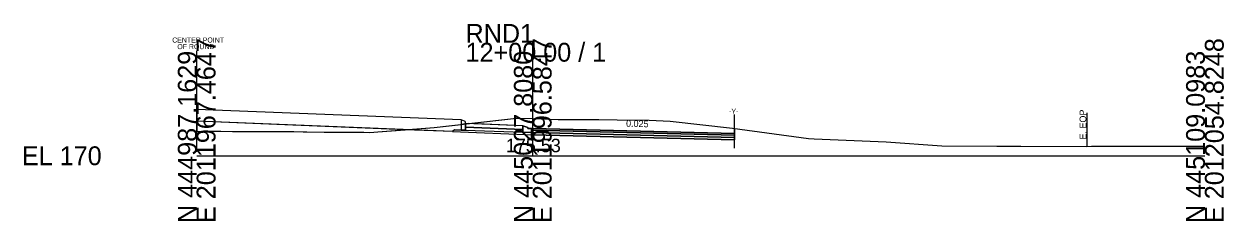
# Model space of a CAD drawing. Extents: x -26 to 153, y -10 to 6017.
# Drawn here: x -25.7 to 152.8, y 3990.3 to 4019.6 of the extents above; entities that cross this region are included whole.
import ezdxf

# ---------------------------------------------------------------- set-up
doc = ezdxf.new("R2010")
doc.units = 0
for name, color, linetype in [('Exist Cross Section Cell', 7, 'Continuous'), ('Exist XS Ground Line', 7, 'Continuous'), ('Prop CMT Conc Surface', 7, 'Continuous'), ('Prop CMT Concrete Structures', 7, 'Continuous'), ('Prop CMT Pvmt Course 1', 7, 'Continuous'), ('Prop CMT Pvmt Course 1 CG', 7, 'Continuous'), ('Prop CMT Pvmt Course 2', 7, 'Continuous'), ('Prop CMT Pvmt Course 3', 7, 'Continuous'), ('Prop CMT Pvmt Surface', 7, 'Continuous'), ('Prop CMT Shear Line', 7, 'Continuous'), ('Prop CMT Shear Line Text', 7, 'Continuous'), ('Prop CMT Slope Grass', 7, 'Continuous'), ('Prop CMT Subgrade Earthwork', 7, 'Continuous'), ('Prop XS Earthwork Shape', 7, 'Continuous'), ('Prop XS Label Text', 7, 'Continuous'), ('Prop XS SE Text', 7, 'Continuous')]:
    doc.layers.add(name, color=color, linetype=linetype)

msp = doc.modelspace()

# ---------------------------------------------------------------- linework, layer by layer
at = {"layer": 'Exist Cross Section Cell'}
for p, q in [((50, 4000), (50, 4016.79)), ((0, 4000), (50, 4000)), ((50, 4000), (150, 4000))]:
    msp.add_line(p, q, dxfattribs=at)
at = {"layer": 'Exist XS Ground Line'}
msp.add_lwpolyline([(0, 4003.62), (0.51, 4003.62), (1.76, 4003.64), (3.57, 4003.66), (5.34, 4003.63), (6.64, 4003.61), (7.81, 4003.62), (9.98, 4003.63), (11.22, 4003.61), (12.43, 4003.6), (12.79, 4003.6), (14.46, 4003.59), (15.85, 4003.57), (16.4, 4003.57), (18.96, 4003.53), (19.68, 4003.53), (20.69, 4003.53), (21.99, 4003.52), (22.86, 4003.51), (23.37, 4003.5), (24.89, 4003.5), (25.76, 4003.44), (26.95, 4003.56), (35.33, 4004.22), (47.6, 4005.58), (48.08, 4005.6), (50, 4005.53), (53.77, 4005.4), (59.84, 4005.39), (62.55, 4005.35), (67.34, 4005.28), (70.42, 4005.13), (79.71, 4004.08), (91.03, 4002.59), (91.86, 4002.53), (102.6, 4002.07), (110.88, 4001.48), (119.04, 4001.41), (122.62, 4001.41), (132.45, 4001.4), (133.12, 4001.41), (134.27, 4001.41), (135.46, 4001.42), (135.96, 4001.42), (136.61, 4001.41), (138.87, 4001.42), (140.9, 4001.42), (141.52, 4001.42), (141.96, 4001.42), (143.31, 4001.43), (145.21, 4001.45), (148.11, 4001.45), (148.68, 4001.44), (149.49, 4001.44), (150, 4001.44)], dxfattribs=at)
at = {"layer": 'Prop CMT Conc Surface'}
for points in [[(40, 4005), (39.96, 4005.1), (39.85, 4005.15), (39.34, 4005.33)], [(40, 4004.83), (40, 4005)], [(50, 4004.04), (49.25, 4004.06), (49.25, 4004.22), (48.5, 4004.47)]]:
    msp.add_lwpolyline(points, dxfattribs=at)
at = {"layer": 'Prop CMT Concrete Structures'}
for points in [[(40, 4005), (39.96, 4005.1), (39.85, 4005.15), (39.34, 4005.33)], [(39.34, 4005.33), (39.34, 4003.83)], [(40, 4004.83), (40, 4005)], [(40, 4003.83), (40, 4004.83)], [(40, 4004.83), (40, 4004.25)], [(48.5, 4004.47), (40, 4004.82)], [(39.34, 4003.83), (40, 4003.83)], [(40, 4004.23), (48.5, 4003.89)], [(50, 4004.04), (49.25, 4004.06), (49.25, 4004.22), (48.5, 4004.47)], [(48.5, 4004.47), (48.5, 4003.49)], [(48.5, 4003.89), (48.5, 4004.47)], [(48.5, 4003.49), (50, 4003.46)], [(50, 4003.46), (50, 4004.04)]]:
    msp.add_lwpolyline(points, dxfattribs=at)
at = {"layer": 'Prop CMT Pvmt Course 1'}
for points in [[(50, 4004.04), (80, 4003.29)], [(50, 4003.79), (50, 4004.04)], [(80, 4003.04), (50, 4003.79)], [(80, 4003.29), (80, 4003.04)]]:
    msp.add_lwpolyline(points, dxfattribs=at)
msp.add_lwpolyline([(50, 4003.79), (50, 4003.91), (50, 4003.91), (50, 4003.79)], close=True, dxfattribs=at)
at = {"layer": 'Prop CMT Pvmt Course 1 CG'}
for points in [[(50, 4003.12), (50, 4003.46)], [(80, 4002.37), (80, 4002.7)]]:
    msp.add_lwpolyline(points, dxfattribs=at)
at = {"layer": 'Prop CMT Pvmt Course 2'}
for points in [[(50, 4003.46), (50, 4003.79)], [(50, 4003.79), (80, 4003.04)], [(80, 4002.7), (50, 4003.46)], [(80, 4003.04), (80, 4002.7)]]:
    msp.add_lwpolyline(points, dxfattribs=at)
at = {"layer": 'Prop CMT Pvmt Course 3'}
for points in [[(40, 4003.83), (48.5, 4003.49)], [(50, 4003.46), (80, 4002.7)], [(50, 4003.12), (50, 4003.46)], [(80, 4002.37), (50, 4003.12)], [(80, 4002.7), (80, 4002.37)]]:
    msp.add_lwpolyline(points, dxfattribs=at)
at = {"layer": 'Prop CMT Pvmt Surface'}
msp.add_lwpolyline([(50, 4004.04), (80, 4003.29)], dxfattribs=at)
at = {"layer": 'Prop CMT Shear Line'}
for p, q in [((0, 4000.58), (0, 4015.58)), ((80, 4001.11), (80, 4006.12))]:
    msp.add_line(p, q, dxfattribs=at)
at = {"layer": 'Prop CMT Slope Grass'}
for p, q in [((39.34, 4005.32), (0, 4006.89)), ((38.06, 4003.6), (0, 4005.12))]:
    msp.add_line(p, q, dxfattribs=at)
at = {"layer": 'Prop CMT Subgrade Earthwork'}
for p, q in [((0, 4006.89), (0, 4003.62)), ((38.34, 4003.87), (38.06, 4003.6)), ((80, 4002.37), (80, 4004.04))]:
    msp.add_line(p, q, dxfattribs=at)
for points in [[(38.06, 4003.6), (50, 4003.12)], [(38.34, 4003.87), (39.34, 4003.83)], [(50, 4003.12), (80, 4002.37)]]:
    msp.add_lwpolyline(points, dxfattribs=at)
at = {"layer": 'Prop XS Earthwork Shape'}
for points in [[(21.99, 4003.52), (22.86, 4003.51), (23.37, 4003.5), (24.89, 4003.5), (25.76, 4003.44), (26.95, 4003.56), (31.02, 4003.88), (0, 4005.12), (0, 4003.62), (0.51, 4003.62), (1.76, 4003.64), (3.57, 4003.66), (5.34, 4003.63), (6.64, 4003.61), (7.81, 4003.62), (9.98, 4003.63), (11.22, 4003.61), (12.43, 4003.6), (12.79, 4003.6), (14.46, 4003.59), (15.85, 4003.57), (16.4, 4003.57), (18.96, 4003.53), (19.68, 4003.53), (20.69, 4003.53)], [(38.34, 4003.87), (38.06, 4003.6), (31.02, 4003.88), (35.33, 4004.22), (39.34, 4004.66), (39.34, 4003.83)], [(40, 4004.23), (40, 4004.25), (40, 4004.74), (39.34, 4004.66), (39.34, 4003.83), (40, 4003.83)], [(48.5, 4003.89), (48.5, 4004.47), (40.51, 4004.79), (40, 4004.74), (40, 4004.25), (40, 4004.23)], [(48.5, 4004.47), (40.51, 4004.79), (47.6, 4005.58), (48.08, 4005.6), (50, 4005.53), (53.77, 4005.4), (59.84, 4005.39), (62.55, 4005.35), (67.34, 4005.28), (70.42, 4005.13), (79.71, 4004.08), (80, 4004.04), (80, 4003.29), (50, 4004.04), (49.25, 4004.06), (49.25, 4004.22)], [(48.5, 4003.49), (48.5, 4003.89), (40, 4004.23), (40, 4003.83), (39.34, 4003.83), (38.34, 4003.87), (38.06, 4003.6), (50, 4003.12), (80, 4002.37), (80, 4003.29), (50, 4004.04), (50, 4003.46)], [(48.5, 4003.89), (48.5, 4004.47), (49.25, 4004.22), (49.25, 4004.06), (50, 4004.04), (50, 4003.46), (48.5, 4003.49)]]:
    msp.add_lwpolyline(points, close=True, dxfattribs=at)
at = {"layer": 'Prop XS Label Text'}
msp.add_line((132.45, 4006.4), (132.45, 4001.4), dxfattribs=at)

# ---------------------------------------------------------------- texts
at = {"layer": 'Exist Cross Section Cell'}
for s, p in [('RND1', (40, 4016.79)), ('12+00.00 / 1', (40, 4013.99)), ('EL 170', (-26, 3998.6))]:
    msp.add_text(s, height=2.8, dxfattribs=at).set_placement(p)
for s, p in [('E 2011967.4647', (2.8, 3990)), ('E 2011996.5847', (52.8, 3990)), ('E 2012054.8248', (152.8, 3990)), ('N 444987.1629', (0, 3990)), ('N 445027.8080', (50, 3990)), ('N 445109.0983', (150, 3990))]:
    msp.add_text(s, height=2.8, rotation=90, dxfattribs=at).set_placement(p)
at = {"layer": 'Exist XS Ground Line'}
msp.add_text('175.53', height=2, dxfattribs=at).set_placement((45.99, 4000.53))
at = {"layer": 'Prop CMT Shear Line Text'}
for s, p in [('CENTER POINT', (-3.64, 4016.83)), ('OF ROUND', (-2.88, 4015.85)), ('-Y-', (79.21, 4006.24))]:
    msp.add_text(s, height=0.75, dxfattribs=at).set_placement(p)
at = {"layer": 'Prop XS Label Text'}
msp.add_text('E. EOP', height=1, rotation=90, dxfattribs=at).set_placement((132.35, 4002.41))
at = {"layer": 'Prop XS SE Text'}
msp.add_text('0.025', height=1, rotation=358.5613, dxfattribs=at).set_placement((63.87, 4004.32))

doc.saveas('drawing.dxf')
